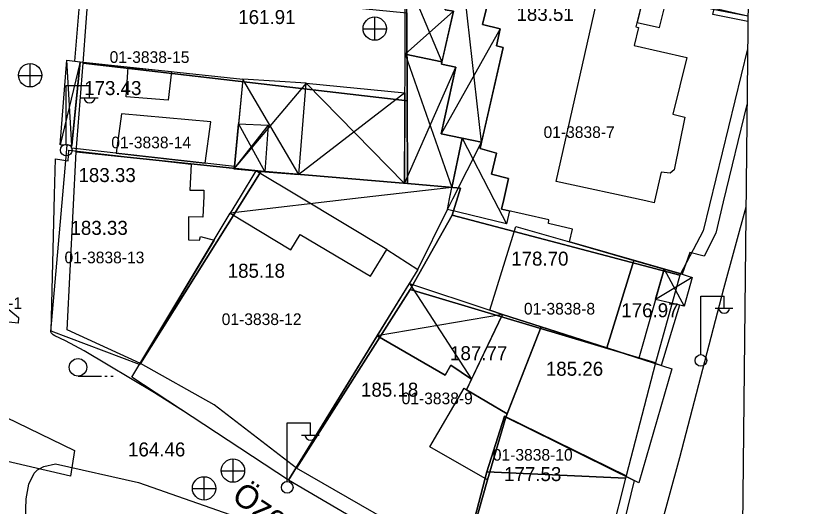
# Model space of a CAD drawing. Extents: x 419101 to 420177, y 4451541 to 4452254.
# Drawn here: x 420104.4 to 420173.1, y 4451623.9 to 4451666 of the extents above; entities that cross this region are included whole.
import ezdxf

# ---------------------------------------------------------------- set-up
doc = ezdxf.new("R2010")
doc.units = 0
for name, color, linetype in [('0_ÖNERİ_LEJAND', 7, 'Continuous'), ('2_KADASTRO', 7, 'Continuous'), ('3_HALİHAZIR', 7, 'Continuous'), ('Level 10', 7, 'Continuous')]:
    doc.layers.add(name, color=color, linetype=linetype)

msp = doc.modelspace()

# ---------------------------------------------------------------- linework, layer by layer
at = {"layer": '0_ÖNERİ_LEJAND'}
msp.add_lwpolyline([(419108.722, 4452245.778), (420173.096, 4452234.536), (420165.768, 4451540.511), (419101.295, 4451551.753)], close=True, dxfattribs=at)
at = {"layer": '2_KADASTRO'}
msp.add_lwpolyline([(420167.064, 4451663.227), (420163.25, 4451647.61), (420161.27, 4451643.82), (420141.77, 4451648.95), (420142.48, 4451651.27), (420137.929, 4451651.66), (420137.915, 4451658.749), (420137.878, 4451666.312), (420137.855, 4451673.012), (420158.379, 4451668.084), (420167.093, 4451666.045)], dxfattribs=at)
for points in [[(420110.14, 4451661.99), (420110.657, 4451669.001), (420137.878, 4451666.312), (420137.915, 4451658.749), (420137.444, 4451658.804)], [(420109.56, 4451654.38), (420110.14, 4451661.99), (420137.444, 4451658.804), (420137.915, 4451658.749), (420137.929, 4451651.66), (420136.88, 4451651.75), (420125.41, 4451652.74)], [(420109.56, 4451654.38), (420125.41, 4451652.74), (420115.05, 4451636.24), (420108.79, 4451639.12)], [(420115.05, 4451636.24), (420125.41, 4451652.74), (420136.88, 4451651.75), (420137.929, 4451651.66), (420142.48, 4451651.27), (420141.77, 4451648.95), (420138.154, 4451642.594), (420128.43, 4451627.26), (420121.379, 4451632.703)], [(420138.154, 4451642.594), (420141.77, 4451648.95), (420161.27, 4451643.82), (420159.18, 4451636.29)], [(420100.985, 4451643.163), (420104.616, 4451640.189), (420104.585, 4451639.707), (420099.994, 4451640.173)], [(420128.43, 4451627.26), (420138.154, 4451642.594), (420159.18, 4451636.29), (420156.66, 4451626.604), (420146.254, 4451631.742), (420144.726, 4451626.966), (420142.68, 4451619.06)], [(420093.774, 4451634.953), (420102.495, 4451632.124), (420109.404, 4451628.798), (420109.076, 4451626.572), (420095.93, 4451629.643), (420087.429, 4451631.629), (420075.491, 4451635.071), (420075.337, 4451636.563), (420085.736, 4451636.352)], [(420144.726, 4451626.966), (420146.254, 4451631.742), (420156.66, 4451626.604), (420156.61, 4451626.41)], [(420142.68, 4451619.06), (420144.726, 4451626.966), (420156.61, 4451626.41), (420154.15, 4451616.69)]]:
    msp.add_lwpolyline(points, close=True, dxfattribs=at)
at = {"layer": '3_HALİHAZIR'}
for p, q in [((420144.283, 4451655.217), (420142.392, 4451671.852)), ((420138.585, 4451667.556), (420140.875, 4451662.087)), ((420135.141, 4451663.941), (420135.141, 4451665.941)), ((420137.721, 4451662.772), (420141.877, 4451666.434)), ((420134.121, 4451664.931), (420136.121, 4451664.931)), ((420145.875, 4451664.937), (420140.815, 4451655.94)), ((420137.721, 4451662.772), (420141.739, 4451651.343)), ((420105.619, 4451659.938), (420105.619, 4451661.938)), ((420109.9, 4451662.09), (420108.182, 4451654.995)), ((420109.166, 4451654.929), (420108.754, 4451662.233)), ((420137.68, 4451651.682), (420142.082, 4451661.642)), ((420104.599, 4451660.928), (420106.599, 4451660.928)), ((420128.621, 4451652.439), (420123.824, 4451660.618)), ((420108.692, 4451655.059), (420108.692, 4451660.059)), ((420108.692, 4451660.059), (420110.692, 4451660.059)), ((420110.692, 4451659.059), (420110.692, 4451660.059)), ((420129.263, 4451660.283), (420123.066, 4451652.92)), ((420129.263, 4451660.283), (420137.68, 4451651.682)), ((420109.932, 4451659.019), (420111.432, 4451659.019)), ((420137.709, 4451659.454), (420128.621, 4451652.439)), ((420125.989, 4451656.665), (420123.066, 4451652.92)), ((420123.46, 4451656.788), (420125.719, 4451652.681)), ((420142.606, 4451655.567), (420145.332, 4451650.312)), ((420141.81, 4451650.349), (420144.283, 4451655.217)), ((420128.713, 4451650.487), (420124.946, 4451652.746)), ((420141.739, 4451651.343), (420133.961, 4451650.432)), ((420133.961, 4451650.432), (420122.748, 4451649.119)), ((420136.168, 4451646.018), (420128.713, 4451650.487)), ((420141.35, 4451649.444), (420141.81, 4451650.349)), ((420145.332, 4451650.312), (420146.423, 4451648.209)), ((420159.921, 4451644.34), (420161.645, 4451641.149)), ((420162.333, 4451643.611), (420159.187, 4451641.74)), ((420138.092, 4451643.112), (420143.428, 4451634.909)), ((420163.053, 4451637.027), (420163.053, 4451642.027)), ((420163.053, 4451642.027), (420165.053, 4451642.027)), ((420165.053, 4451641.027), (420165.053, 4451642.027)), ((420146.079, 4451640.446), (420135.323, 4451638.603)), ((420164.293, 4451640.987), (420165.793, 4451640.987)), ((420109.707, 4451635.168), (420111.707, 4451635.168)), ((420112.007, 4451635.168), (420112.207, 4451635.168)), ((420112.507, 4451635.168), (420112.707, 4451635.168)), ((420127.615, 4451626.15), (420127.615, 4451631.15)), ((420127.615, 4451631.15), (420129.615, 4451631.15)), ((420129.615, 4451630.15), (420129.615, 4451631.15)), ((420128.855, 4451630.11), (420130.355, 4451630.11)), ((420122.996, 4451626.055), (420122.996, 4451628.055)), ((420121.976, 4451627.045), (420123.976, 4451627.045)), ((420120.518, 4451624.534), (420120.518, 4451626.534)), ((420119.498, 4451625.524), (420121.498, 4451625.524))]:
    msp.add_line(p, q, dxfattribs=at)
for points in [[(420137.721, 4451662.772), (420137.77, 4451672.872), (420139.761, 4451672.433), (420142.392, 4451671.852), (420141.253, 4451666.943), (420141.167, 4451666.572), (420141.877, 4451666.434), (420140.875, 4451662.087)], [(420147.613, 4451670.661), (420147.613, 4451670.661), (420147.968, 4451670.579), (420147.53, 4451668.97), (420145.36, 4451669.401), (420144.352, 4451665.307), (420145.875, 4451664.937), (420145.567, 4451663.46), (420146.133, 4451663.321), (420144.283, 4451655.217), (420140.815, 4451655.94), (420142.082, 4451661.642), (420140.832, 4451661.901), (420141.877, 4451666.434), (420141.167, 4451666.572), (420142.392, 4451671.852)], [(420137.68, 4451651.682), (420137.721, 4451662.772), (420140.875, 4451662.087), (420140.832, 4451661.901), (420142.082, 4451661.642), (420140.815, 4451655.94), (420142.606, 4451655.567), (420141.739, 4451651.343)], [(420109.9, 4451662.09), (420109.166, 4451654.929), (420108.182, 4451654.995), (420108.754, 4451662.233)], [(420123.112, 4451653.123), (420109.142, 4451654.698), (420109.9, 4451662.09), (420123.824, 4451660.618)], [(420113.819, 4451659.102), (420113.994, 4451661.657), (420117.704, 4451661.265), (420117.423, 4451658.802)], [(420128.621, 4451652.439), (420129.263, 4451660.283), (420123.824, 4451660.618), (420123.46, 4451656.788), (420123.112, 4451653.123), (420123.066, 4451652.92), (420124.946, 4451652.746), (420125.719, 4451652.681)], [(420129.263, 4451660.283), (420137.709, 4451659.454), (420137.68, 4451651.682), (420128.621, 4451652.439)], [(420113.433, 4451657.652), (420112.975, 4451654.266), (420120.613, 4451653.405), (420121.088, 4451656.972)], [(420123.46, 4451656.788), (420125.989, 4451656.665), (420125.719, 4451652.681), (420124.946, 4451652.746), (420123.066, 4451652.92), (420123.112, 4451653.123)], [(420127.737, 4451626.247), (420114.326, 4451635.076), (420122.748, 4451649.119), (420127.934, 4451645.983), (420128.75, 4451647.302), (420134.774, 4451643.742), (420136.168, 4451646.018), (420138.824, 4451644.304)], [(420157.327, 4451645.081), (420155.014, 4451637.573), (420149.383, 4451639.382), (420146.079, 4451640.446), (420144.994, 4451640.822), (420147.201, 4451647.984), (420151.806, 4451646.66)], [(420155.014, 4451637.573), (420157.327, 4451645.081), (420159.921, 4451644.34), (420157.761, 4451636.691)], [(420161.223, 4451641.25), (420159.657, 4451636.082), (420157.761, 4451636.691), (420155.014, 4451637.573), (420157.327, 4451645.081), (420159.921, 4451644.34), (420161.466, 4451643.898), (420162.333, 4451643.611), (420161.645, 4451641.149)], [(420159.19, 4451641.753), (420159.921, 4451644.34), (420161.466, 4451643.898), (420162.333, 4451643.611), (420161.645, 4451641.149), (420159.187, 4451641.74)], [(420138.092, 4451643.112), (420144.994, 4451640.822), (420146.079, 4451640.446), (420143.428, 4451634.909), (420141.659, 4451636.089), (420141.153, 4451635.231), (420135.323, 4451638.603)], [(420146.466, 4451631.937), (420142.992, 4451633.999), (420146.079, 4451640.446), (420149.383, 4451639.382)], [(420157.744, 4451626.003), (420146.351, 4451631.643), (420149.383, 4451639.382), (420160.591, 4451635.782)], [(420141.825, 4451617.979), (420127.737, 4451626.247), (420135.323, 4451638.603), (420141.153, 4451635.231), (420141.659, 4451636.089), (420143.428, 4451634.909), (420142.992, 4451633.999), (420146.466, 4451631.937), (420146.351, 4451631.643), (420144.796, 4451626.259), (420142.747, 4451619.105)], [(420142.992, 4451633.999), (420146.466, 4451631.937), (420146.351, 4451631.643), (420144.796, 4451626.259), (420139.859, 4451629.086), (420142.781, 4451634.138)], [(420154.796, 4451615.786), (420142.397, 4451618.677), (420142.747, 4451619.105), (420144.796, 4451626.259), (420146.351, 4451631.643), (420157.343, 4451626.201)]]:
    msp.add_lwpolyline(points, close=True, dxfattribs=at)
for points in [[(420146.182, 4451650.303), (420146.58, 4451652.103), (420145.14, 4451652.474), (420145.563, 4451654.282), (420144.156, 4451654.662), (420146.133, 4451663.321), (420145.567, 4451663.46), (420145.875, 4451664.937), (420144.352, 4451665.307), (420145.36, 4451669.401), (420147.53, 4451668.97), (420147.968, 4451670.579), (420150.637, 4451669.963), (420154.8, 4451668.878), (420158.229, 4451668.091), (420157.596, 4451665.482), (420159.53, 4451665.038), (420160.161, 4451667.589), (420164.1, 4451666.625), (420167.093, 4451666.033)], [(420158.348, 4451650.174), (420150.659, 4451651.83), (420154.512, 4451668.944), (420158.229, 4451668.091), (420157.503, 4451665.097), (420157.73, 4451665.041), (420157.357, 4451663.512), (420161.873, 4451662.486), (420160.675, 4451657.622), (420161.696, 4451657.361), (420160.77, 4451652.839), (420160.422, 4451652.564), (420159.661, 4451652.643), (420159.09, 4451650.167)], [(420109.421, 4451662.15), (420109.845, 4451666.971)], [(420167.013, 4451658.432), (420164.989, 4451650.104)], [(420141.536, 4451650.352), (420142.606, 4451655.567), (420144.283, 4451655.217), (420144.156, 4451654.662), (420145.563, 4451654.282), (420145.14, 4451652.474), (420146.58, 4451652.103), (420146.182, 4451650.303)], [(420108.675, 4451653.655), (420108.79, 4451654.954)], [(420107.689, 4451650.709), (420107.765, 4451653.797), (420108.869, 4451653.625), (420108.927, 4451654.532), (420119.389, 4451653.335), (420119.28, 4451651.1), (420120.498, 4451651.112), (420120.476, 4451650.574)], [(420108.416, 4451650.702), (420108.675, 4451653.655)], [(420141.536, 4451650.352), (420141.739, 4451651.343), (420124.946, 4451652.746), (420123.61, 4451650.541)], [(420120.476, 4451650.574), (420120.403, 4451648.78), (420119.173, 4451648.801), (420119.173, 4451646.853), (420120.117, 4451646.816), (420120.213, 4451647.131), (420121.363, 4451646.809), (420114.972, 4451636.152), (420107.402, 4451639.001), (420107.689, 4451650.709)], [(420110.228, 4451637.331), (420108.647, 4451638.172), (420107.726, 4451638.6), (420107.567, 4451638.705), (420107.416, 4451638.885), (420107.387, 4451638.984), (420108.416, 4451650.702)], [(420123.61, 4451650.541), (420122.748, 4451649.119), (420127.934, 4451645.983), (420128.75, 4451647.302), (420134.774, 4451643.742), (420136.168, 4451646.018), (420138.824, 4451644.304), (420141.35, 4451649.444), (420141.536, 4451650.352)], [(420146.182, 4451650.303), (420145.998, 4451649.472), (420146.67, 4451649.321), (420146.423, 4451648.209), (420141.35, 4451649.444), (420141.536, 4451650.352)], [(420164.989, 4451650.104), (420164.333, 4451647.408), (420163.351, 4451645.431), (420162.108, 4451645.771), (420161.466, 4451643.898), (420151.806, 4451646.66), (420152.065, 4451647.765), (420150.017, 4451648.241), (420150.049, 4451648.563), (420145.998, 4451649.472), (420146.182, 4451650.303)], [(420159.09, 4451650.167), (420159.057, 4451650.022), (420158.348, 4451650.174)], [(420166.92, 4451649.646), (420165.012, 4451642.63), (420161.222, 4451628.166), (420158.675, 4451618.742), (420158.569, 4451618.308)], [(420119.046, 4451631.969), (420116.254, 4451633.73), (420110.228, 4451637.331)], [(420105.211, 4451622.908), (420105.272, 4451624.653), (420105.506, 4451625.887), (420105.937, 4451626.832), (420106.243, 4451627.127), (420106.772, 4451627.425), (420107.773, 4451627.648), (420114.88, 4451626.056), (420123.847, 4451622.888)]]:
    msp.add_lwpolyline(points, dxfattribs=at)
for centre, radius in [((420135.126, 4451664.949), 1), ((420105.604, 4451660.946), 1), ((420108.702, 4451654.534), 0.5), ((420163.064, 4451636.503), 0.5), ((420109.707, 4451635.918), 0.75), ((420122.98, 4451627.063), 1), ((420120.503, 4451625.542), 1), ((420127.625, 4451625.626), 0.5)]:
    msp.add_circle(centre, radius, dxfattribs=at)
for centre in [(420110.692, 4451659.062), (420165.054, 4451641.031), (420129.615, 4451630.154)]:
    msp.add_arc(centre, 0.474, 184.83843, 355.14641, dxfattribs=at)
at = {"layer": 'Level 10'}
msp.add_lwpolyline([(420167.088, 4451665.557), (420164.079, 4451666.161), (420167.241, 4451680.004)], dxfattribs=at)

# ---------------------------------------------------------------- texts
at = {"layer": '2_KADASTRO'}
for s, p in [('01-3838-15', (420112.415, 4451662.008)), ('01-3838-7', (420149.588, 4451655.575)), ('01-3838-14', (420112.555, 4451654.689)), ('01-3838-13', (420108.549, 4451644.833)), ('01-3834-1', (420098.817, 4451640.916)), ('01-3838-8', (420147.905, 4451640.439)), ('01-3838-12', (420122.017, 4451639.54)), ('01-3838-9', (420137.429, 4451632.75)), ('01-3838-10', (420145.242, 4451627.913))]:
    msp.add_text(s, height=1, dxfattribs=at).set_placement(p)
at = {"layer": '3_HALİHAZIR'}
for s, height, rotation, p in [('161.91 ', 1.2, 359.99714, (420123.432, 4451665.34)), ('173.43 ', 1.2, 359.99793, (420110.232, 4451659.252)), ('164.46 ', 1.2, 0.00203, (420113.991, 4451628.276)), ('Özen Sokak', 2, 326.8811, (420122.765, 4451624.531))]:
    msp.add_text(s, height=height, rotation=rotation, dxfattribs=at).set_placement(p)
for s, p in [('183.51', (420147.269, 4451665.607)), ('183.33', (420109.746, 4451651.797)), ('183.33', (420109.061, 4451647.27)), ('178.70', (420146.814, 4451644.63)), ('185.18', (420122.53, 4451643.595)), ('176.97', (420156.248, 4451640.205)), ('187.77', (420141.579, 4451636.528)), ('185.26', (420149.785, 4451635.193)), ('185.18', (420133.948, 4451633.398)), ('177.53', (420146.205, 4451626.162))]:
    msp.add_text(s, height=1.2, dxfattribs=at).set_placement(p)

doc.saveas('drawing.dxf')
